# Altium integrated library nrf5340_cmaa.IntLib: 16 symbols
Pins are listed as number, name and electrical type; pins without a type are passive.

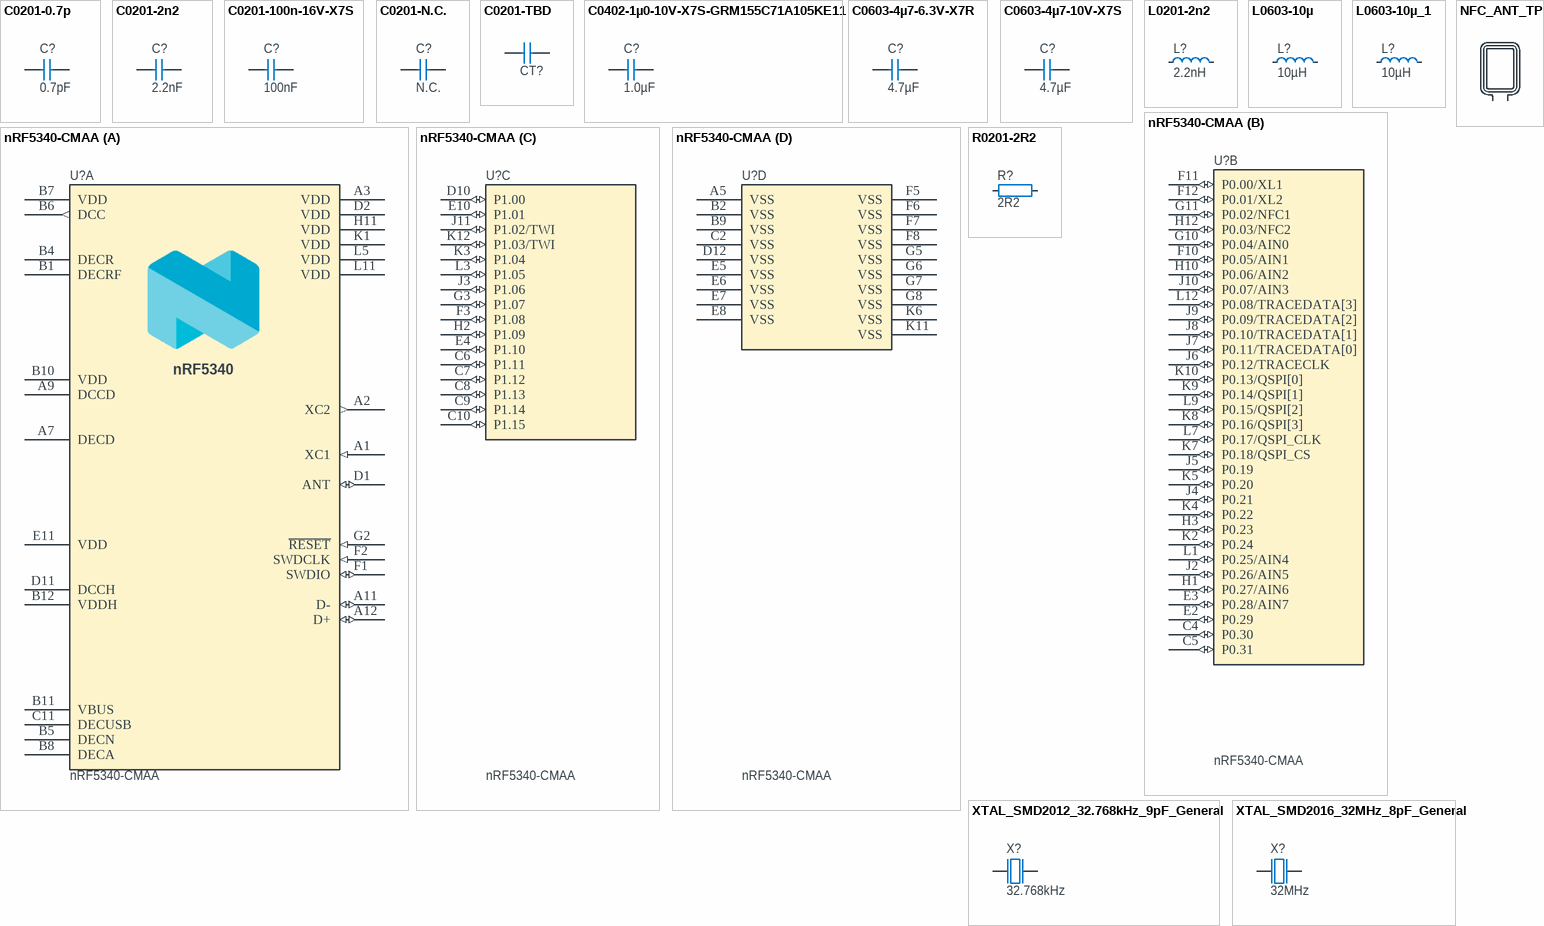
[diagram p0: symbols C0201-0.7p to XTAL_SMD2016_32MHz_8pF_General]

## C0201-0.7p
designator C?, comment 0.7pF
Capacitor, NP0, ±0.05pF; Pad Count: 2
footprint CAPC0603X03L_C
pins: 1, 2

## C0201-2n2
designator C?, comment 2.2nF
Capacitor, X7R, ±10%; Pad Count: 2
footprint CAPC0603X03L_C
pins: 1, 2

## C0201-100n-16V-X7S
designator C?, comment 100nF
Capacitor, X7S, ±10%; Pad Count: 2
footprint CAPC0603X03L_C
pins: 1, 2

## C0201-N.C.
designator C?, comment N.C.
Not mounted; Assembly: Not mounted; Pad Count: 2
footprint CAPC0603X03L_C_NC
pins: 1, 2

## C0201-TBD
designator CT?, comment Antenna dependent  (value not drawn)
Capacitor, NP0, ±5%; Pad Count: 2
footprint CAPC0603X03L_C
pins: 1, 2

## C0402-1µ0-10V-X7S-GRM155C71A105KE11
designator C?, comment 1.0µF
Capacitor, X7S, ±10%; Pad Count: 2
footprint CAPC1005X04L
pins: 1, 2

## C0603-4µ7-6.3V-X7R
designator C?, comment 4.7µF
Capacitor, X7R, ±10%; Pad Count: 2
footprint CAPC1608X06L
pins: 1, 2

## C0603-4µ7-10V-X7S
designator C?, comment 4.7µF
Capacitor, X7S, ±10%; Pad Count: 2
footprint CAPC1608X06L
pins: 1, 2

## L0201-2n2
designator L?, comment 2.2nH
High frequency chip inductor, ±5%; Pad Count: 2
footprint INDC0603X03L_C
pins: 1, 2

## L0603-10µ
designator L?, comment 10µH
Chip inductor, IDC,min = 50 mA, ±20%; Pad Count: 2
footprint INDC1608X06L
pins: 1, 2

## L0603-10µ_1
designator L?, comment 10µH
Chip inductor, IDC,min = 80 mA, ±20%; Pad Count: 2
footprint INDC1608X06L
pins: 1, 2

## NFC_ANT_TP
designator A?, comment NFC Antenna  (value not drawn)  (no BOM)
Pad Count: 2
footprint TP_2x1mm_TH
pins: 1, 2

## nRF5340-CMAA
designator U?
Multi-protocol Bluetooth Low Energy, IEEE 802.15.4, ANT and 2.4GHz proprietary system-on-chip; Manufacturer: Nordic Semiconductor; Pad Count: 95
footprint BGA95C35P12X11_439X399X49
part A pins: A1 XC1 (in), A2 XC2 (out), A3 VDD (power), A7 DECD (power), A9 DCCD (power), A11 D- (io), A12 D+ (io), B1 DECRF (power), B4 DECR (power), B5 DECN (power), B6 DCC (out), B7 VDD (power), B8 DECA (power), B10 VDD (power), B11 VBUS (power), B12 VDDH (power), C11 DECUSB (power), D1 ANT (io), D2 VDD (power), D11 DCCH (power), E11 VDD (power), F1 SWDIO (io), F2 SWDCLK (in), G2 ~{RESET} (in), H11 VDD (power), K1 VDD (power), L5 VDD (power), L11 VDD (power)
part B pins: C4 P0.30 (io), C5 P0.31 (io), E2 P0.29 (io), E3 P0.28/AIN7 (io), F10 P0.05/AIN1 (io), F11 P0.00/XL1 (io), F12 P0.01/XL2 (io), G10 P0.04/AIN0 (io), G11 P0.02/NFC1 (io), H1 P0.27/AIN6 (io), H3 P0.23 (io), H10 P0.06/AIN2 (io), H12 P0.03/NFC2 (io), J2 P0.26/AIN5 (io), J4 P0.21 (io), J5 P0.19 (io), J6 P0.12/TRACECLK (io), J7 P0.11/TRACEDATA[0] (io), J8 P0.10/TRACEDATA[1] (io), J9 P0.09/TRACEDATA[2] (io), J10 P0.07/AIN3 (io), K2 P0.24 (io), K4 P0.22 (io), K5 P0.20 (io), K7 P0.18/QSPI_CS (io), K8 P0.16/QSPI[3] (io), K9 P0.14/QSPI[1] (io), K10 P0.13/QSPI[0] (io), L1 P0.25/AIN4 (io), L7 P0.17/QSPI_CLK (io), L9 P0.15/QSPI[2] (io), L12 P0.08/TRACEDATA[3] (io)
part C pins: C6 P1.11 (io), C7 P1.12 (io), C8 P1.13 (io), C9 P1.14 (io), C10 P1.15 (io), D10 P1.00 (io), E4 P1.10 (io), E10 P1.01 (io), F3 P1.08 (io), G3 P1.07 (io), H2 P1.09 (io), J3 P1.06 (io), J11 P1.02/TWI (io), K3 P1.04 (io), K12 P1.03/TWI (io), L3 P1.05 (io)
part D pins: A5 VSS (power), B2 VSS (power), B9 VSS (power), C2 VSS (power), D12 VSS (power), E5 VSS (power), E6 VSS (power), E7 VSS (power), E8 VSS (power), F5 VSS (power), F6 VSS (power), F7 VSS (power), F8 VSS (power), G5 VSS (power), G6 VSS (power), G7 VSS (power), G8 VSS (power), K6 VSS (power), K11 VSS (power)

## R0201-2R2
designator R?, comment 2R2
Resistor, ±1%, 0.05W; Pad Count: 2
footprint RESC0603X03L_C
pins: 1, 2

## XTAL_SMD2012_32.768kHz_9pF_General
designator X?, comment 32.768kHz
XTAL SMD 2012, 32.768kHz, Cl=9pF, Total Tol: ±50ppm; Pad Count: 2
footprint XTAL_2012
pins: 1 inp, 2 out

## XTAL_SMD2016_32MHz_8pF_General
designator X?, comment 32MHz
XTAL SMD 2016, 32MHz, Cl=8pF, Total Tol: ±30ppm; Pad Count: 4
footprint BT-XTAL_2016
pins: 1 inp, 2 GND hidden to GND, 3 out, 4 GND hidden to GND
